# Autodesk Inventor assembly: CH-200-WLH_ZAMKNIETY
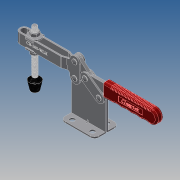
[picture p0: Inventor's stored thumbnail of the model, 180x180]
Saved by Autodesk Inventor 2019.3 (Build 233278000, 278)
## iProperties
Company: Î¢ÈíÖÐ¹ú
Created: 2011-05
Part Number: CH-200-WLH_ZAMKNIETY
Material: Ogólny
Description: STEP AP203
Document SubType Name: Assembly
Designer: CADENGINEERING4
Sending System: SolidWorks 2010
Preprocessor: SwSTEP 2.0
Title: CH-200-WLH.STEP
Author: Î¢ÈíÓÃ»§
Revision Number: ÈÎºÎ
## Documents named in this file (10)
- E:\STRONA\Horizontal toggle clamp\CH-200-WLH\CH-200-WLH_ZAMKNIETY.iam
- E:\STRONA\Horizontal toggle clamp\CH-200-WLH\FW380.ipt
- E:\STRONA\Horizontal toggle clamp\CH-200-WLH\200-W-05.ipt
- E:\STRONA\Horizontal toggle clamp\CH-200-WLH\38312-01.ipt
- E:\STRONA\Horizontal toggle clamp\CH-200-WLH\200-W-04.ipt
- E:\STRONA\Horizontal toggle clamp\CH-200-WLH\200-WLH-01.ipt
- E:\STRONA\Horizontal toggle clamp\CH-200-WLH\200-W-03.ipt
- E:\STRONA\Horizontal toggle clamp\CH-200-WLH\200-WLH-02.ipt
- E:\STRONA\Horizontal toggle clamp\CH-200-WLH\200-W-06.ipt
- E:\STRONA\Horizontal toggle clamp\CH-200-WLH\38412.ipt
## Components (15 placed, 15 different names)
1. FW380_1 — Zestawiające:3, Zestawiające:4, Równoległe:2, Zestawiające:7, Zestawiające:8, Równoległe:3
2. 200-W-05_2 — Zestawiające:14, Zestawiające:16, Zestawiające:28
3. 200-W-05_3 — Zestawiające:26, Zestawiające:27
4. 38312-01_4 — Zestawiające:4, Równoległe:1, Zestawiające:7
5. 200-W-04_5 — Zestawiające:20, Zestawiające:22, Zestawiające:23, Zestawiające:24, Zestawiające:25
6. 200-WLH-01_6 — Zestawiające:19, Zestawiające:20, Zestawiające:21, Zestawiające:22, Zestawiające:28, Zestawiające:29, Przejściowe:1
7. 200-W-03_7 — Zestawiające:11, Zestawiające:17, Zestawiające:18, Zestawiające:30, Zestawiające:31, Zestawiające:32, Przejściowe:1
8. 200-W-04_8 — Zestawiające:19, Zestawiające:21, Zestawiające:23, Zestawiające:26, Zestawiające:27
9. FW380_9 — Zestawiające:2, Równoległe:2, Zestawiające:6, Zestawiające:9
10. 200-WLH-02_10 — Zestawiające:5, Zestawiające:8, Zestawiające:9, Równoległe:3, Zestawiające:13, Zestawiające:14, Zestawiające:15, Zestawiające:16, Zestawiające:29, Zestawiające:30
11. 200-W-05_11 — Zestawiające:24, Zestawiające:25, Zestawiające:32
12. 38312-01_12 — Zestawiające:1, Zestawiające:6
13. 200-W-06_13 — Zestawiające:11, Zestawiające:17, Zestawiające:18
14. 38412_14 — Zestawiające:1, Zestawiające:2, Zestawiające:3, Równoległe:1, Zestawiające:5
15. 200-W-05_15 — Zestawiające:13, Zestawiające:15, Zestawiające:31
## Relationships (34: Mate 30, Flush 3, Transitional 1)
- Zestawiające:1 [Mate]: 38312-01_12 ↔ 38412_14
- Zestawiające:2 [Mate]: FW380_9 ↔ 38412_14
- Zestawiające:3 [Mate]: FW380_1 ↔ 38412_14
- Zestawiające:4 [Mate]: FW380_1 ↔ 38312-01_4
- Równoległe:1 [Flush]: 38312-01_4 ↔ 38412_14
- Równoległe:2 [Flush]: FW380_1 ↔ FW380_9
- Zestawiające:5 [Mate]: 200-WLH-02_10 ↔ 38412_14
- Zestawiające:6 [Mate]: FW380_9 ↔ 38312-01_12
- Zestawiające:7 [Mate]: FW380_1 ↔ 38312-01_4
- Zestawiające:8 [Mate]: FW380_1 ↔ 200-WLH-02_10
- Zestawiające:9 [Mate]: FW380_9 ↔ 200-WLH-02_10
- Równoległe:3 [Flush]: FW380_1 ↔ 200-WLH-02_10
- Zestawiające:11 [Mate]: 200-W-03_7 ↔ 200-W-06_13
- Zestawiające:13 [Mate]: 200-WLH-02_10 ↔ 200-W-05_15
- Zestawiające:14 [Mate]: 200-W-05_2 ↔ 200-WLH-02_10
- Zestawiające:15 [Mate]: 200-WLH-02_10 ↔ 200-W-05_15
- Zestawiające:16 [Mate]: 200-W-05_2 ↔ 200-WLH-02_10
- Zestawiające:17 [Mate]: 200-W-03_7 ↔ 200-W-06_13
- Zestawiające:18 [Mate]: 200-W-03_7 ↔ 200-W-06_13
- Zestawiające:19 [Mate]: 200-WLH-01_6 ↔ 200-W-04_8
- Zestawiające:20 [Mate]: 200-W-04_5 ↔ 200-WLH-01_6
- Zestawiające:21 [Mate]: 200-WLH-01_6 ↔ 200-W-04_8
- Zestawiające:22 [Mate]: 200-W-04_5 ↔ 200-WLH-01_6
- Zestawiające:23 [Mate]: 200-W-04_5 ↔ 200-W-04_8
- Zestawiające:24 [Mate]: 200-W-04_5 ↔ 200-W-05_11
- Zestawiające:25 [Mate]: 200-W-04_5 ↔ 200-W-05_11
- Zestawiające:26 [Mate]: 200-W-05_3 ↔ 200-W-04_8
- Zestawiające:27 [Mate]: 200-W-05_3 ↔ 200-W-04_8
- Zestawiające:28 [Mate]: 200-W-05_2 ↔ 200-WLH-01_6
- Zestawiające:29 [Mate]: 200-WLH-01_6 ↔ 200-WLH-02_10
- Zestawiające:30 [Mate]: 200-W-03_7 ↔ 200-WLH-02_10
- Zestawiające:31 [Mate]: 200-W-03_7 ↔ 200-W-05_15
- Zestawiające:32 [Mate]: 200-W-03_7 ↔ 200-W-05_11
- Przejściowe:1 [Transitional]: 200-WLH-01_6 ↔ 200-W-03_7
